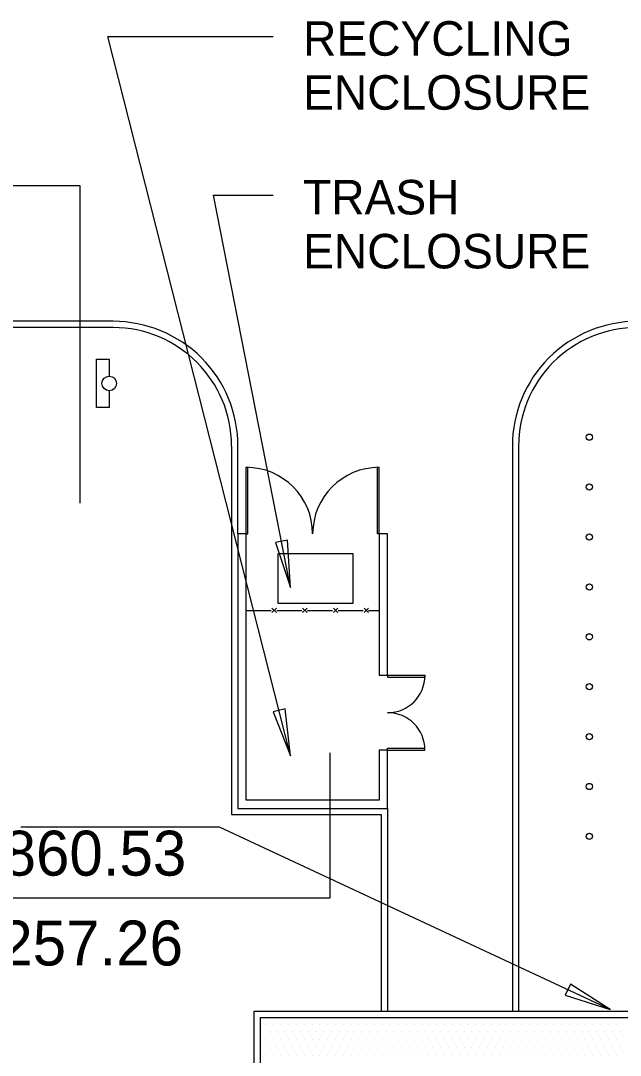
# Model space of a CAD drawing. Extents: x 6712138 to 6712574, y 1869536 to 1870160.
# Drawn here: x 6712232.5 to 6712280.5, y 1869836.3 to 1869919.2 of the extents above; entities that cross this region are included whole.
import ezdxf

# ---------------------------------------------------------------- set-up
doc = ezdxf.new("R2010")
doc.units = 0
for name, color, linetype in [('A-ANNO-TEXT', 7, 'Continuous'), ('A-DETL-GENF', 7, 'Continuous'), ('A-DETL-LW03', 7, 'Continuous'), ('A-DETL-MBND', 7, 'Continuous'), ('A-FLOR-OTLN', 7, 'Continuous'), ('A-FLOR-PATT', 7, 'Continuous'), ('C-PRKG-CONC', 7, 'Continuous'), ('C-SIGN-PARKING', 7, 'Continuous'), ('G-DETL-LW01', 7, 'Continuous'), ('G-DETL-LW03', 7, 'Continuous'), ('I-FURN', 7, 'Continuous'), ('I-WALL', 7, 'Continuous')]:
    doc.layers.add(name, color=color, linetype=linetype)

# ---------------------------------------------------------------- blocks, each defined once
blk = doc.blocks.new('Double-Flush - 10_ x 8_-113-xASP')
at = {"layer": 'A-DETL-MBND'}
for p, q in [((-5.333, 5.667), (-5.187, 5.667)), ((-5.333, 0.333), (-5.333, 5.667)), ((-5.187, 0.333), (-5.187, 5.667)), ((5.187, 0.333), (5.187, 5.665)), ((5.333, 0.333), (5.333, 5.667)), ((-5.333, 0.333), (-5.187, 0.333)), ((5.333, 0.333), (5.187, 0.333))]:
    blk.add_line(p, q, dxfattribs=at)
for centre, start, end in [((-5.333, 0.333), 0, 90), ((5.333, 0.333), 90, 180)]:
    blk.add_arc(centre, 5.333, start, end, dxfattribs=at)
blk = doc.blocks.new('Double-Flush - 6_ x 8_-133-xASP')
at = {"layer": 'A-DETL-MBND'}
for p, q in [((-3, 3.333), (-2.854, 3.333)), ((-3, 0.333), (-3, 3.333)), ((-2.854, 0.333), (-2.854, 3.333)), ((2.854, 0.333), (2.854, 3.33)), ((3, 0.333), (3, 3.333)), ((-3, 0.333), (-2.854, 0.333)), ((3, 0.333), (2.854, 0.333))]:
    blk.add_line(p, q, dxfattribs=at)
for centre, start, end in [((-3, 0.333), 0, 90), ((3, 0.333), 90, 180)]:
    blk.add_arc(centre, 3, start, end, dxfattribs=at)
blk = doc.blocks.new('Repeating Detail - Chain Link Fence-130-xASP')
at = {"layer": 'A-DETL-LW03'}
for p, q in [((0, 0), (2, 0)), ((2.073, 0.177), (2.427, -0.177)), ((2.427, 0.177), (2.073, -0.177))]:
    blk.add_line(p, q, dxfattribs=at)

msp = doc.modelspace()

# ---------------------------------------------------------------- linework, layer by layer
at = {"layer": 'A-ANNO-TEXT'}
for p, q in [((6712239.474, 1869917.929), (6712252.72, 1869917.929)), ((6712254.124, 1869860.283), (6712239.474, 1869917.929)), ((6712239.474, 1869917.929), (6712252.72, 1869917.929)), ((6712254.124, 1869860.283), (6712239.474, 1869917.929)), ((6712247.939, 1869905.209), (6712252.72, 1869905.209)), ((6712254.124, 1869873.783), (6712247.939, 1869905.209)), ((6712247.939, 1869905.209), (6712252.72, 1869905.209)), ((6712254.124, 1869873.783), (6712247.939, 1869905.209)), ((6712253.884, 1869877.558), (6712252.916, 1869877.367)), ((6712253.884, 1869877.558), (6712252.916, 1869877.367)), ((6712253.884, 1869877.558), (6712252.916, 1869877.367)), ((6712253.884, 1869877.558), (6712252.916, 1869877.367)), ((6712252.916, 1869877.367), (6712254.124, 1869873.783)), ((6712252.916, 1869877.367), (6712254.124, 1869873.783)), ((6712252.916, 1869877.367), (6712254.124, 1869873.783)), ((6712252.916, 1869877.367), (6712254.124, 1869873.783)), ((6712254.124, 1869873.783), (6712253.884, 1869877.558)), ((6712254.124, 1869873.783), (6712253.884, 1869877.558)), ((6712254.124, 1869873.783), (6712253.884, 1869877.558)), ((6712254.124, 1869873.783), (6712253.884, 1869877.558)), ((6712253.679, 1869864.039), (6712252.722, 1869863.796)), ((6712253.679, 1869864.039), (6712252.722, 1869863.796)), ((6712253.679, 1869864.039), (6712252.722, 1869863.796)), ((6712253.679, 1869864.039), (6712252.722, 1869863.796)), ((6712252.722, 1869863.796), (6712254.124, 1869860.283)), ((6712252.722, 1869863.796), (6712254.124, 1869860.283)), ((6712252.722, 1869863.796), (6712254.124, 1869860.283)), ((6712252.722, 1869863.796), (6712254.124, 1869860.283)), ((6712254.124, 1869860.283), (6712253.679, 1869864.039)), ((6712254.124, 1869860.283), (6712253.679, 1869864.039)), ((6712254.124, 1869860.283), (6712253.679, 1869864.039)), ((6712254.124, 1869860.283), (6712253.679, 1869864.039)), ((6712241.186, 1869854.578), (6712232.499, 1869854.578)), ((6712241.186, 1869854.578), (6712232.499, 1869854.578)), ((6712248.427, 1869854.578), (6712241.186, 1869854.578)), ((6712248.427, 1869854.578), (6712241.186, 1869854.578)), ((6712279.74, 1869839.953), (6712248.427, 1869854.578)), ((6712279.74, 1869839.953), (6712248.427, 1869854.578)), ((6712276.551, 1869841.987), (6712276.133, 1869841.093)), ((6712276.551, 1869841.987), (6712276.133, 1869841.093)), ((6712276.551, 1869841.987), (6712276.133, 1869841.093)), ((6712276.551, 1869841.987), (6712276.133, 1869841.093)), ((6712279.74, 1869839.953), (6712276.551, 1869841.987)), ((6712279.74, 1869839.953), (6712276.551, 1869841.987)), ((6712279.74, 1869839.953), (6712276.551, 1869841.987)), ((6712279.74, 1869839.953), (6712276.551, 1869841.987)), ((6712276.133, 1869841.093), (6712279.74, 1869839.953)), ((6712276.133, 1869841.093), (6712279.74, 1869839.953)), ((6712276.133, 1869841.093), (6712279.74, 1869839.953)), ((6712276.133, 1869841.093), (6712279.74, 1869839.953))]:
    msp.add_line(p, q, dxfattribs=at)
at = {"layer": 'A-DETL-GENF'}
for p, q in [((6712250.557, 1869878.073), (6712249.89, 1869878.073)), ((6712249.89, 1869878.073), (6712249.89, 1869856.073)), ((6712250.557, 1869856.739), (6712250.557, 1869878.073)), ((6712261.89, 1869878.073), (6712261.224, 1869878.073)), ((6712261.224, 1869878.073), (6712261.224, 1869866.739)), ((6712261.89, 1869866.739), (6712261.89, 1869878.073)), ((6712261.224, 1869866.739), (6712261.89, 1869866.739)), ((6712261.224, 1869860.739), (6712261.224, 1869856.739)), ((6712261.89, 1869860.739), (6712261.224, 1869860.739)), ((6712261.89, 1869856.073), (6712261.89, 1869860.739)), ((6712261.224, 1869856.739), (6712250.557, 1869856.739)), ((6712249.89, 1869856.073), (6712261.89, 1869856.073))]:
    msp.add_line(p, q, dxfattribs=at)
at = {"layer": 'A-FLOR-OTLN'}
for points in [[(6712251.183, 1869839.781), (6712251.183, 1869722.323), (6712419.14, 1869722.323), (6712419.14, 1869718.864), (6712468.641, 1869718.864), (6712468.641, 1869839.781)], [(6712251.683, 1869839.281), (6712251.683, 1869722.823), (6712419.64, 1869722.823), (6712419.64, 1869719.364), (6712468.141, 1869719.364), (6712468.141, 1869839.281)]]:
    msp.add_lwpolyline(points, close=True, dxfattribs=at)
at = {"layer": 'A-FLOR-PATT'}
for p, q in [((6712251.774, 1869838.157), (6712251.774, 1869838.157)), ((6712252.087, 1869838.782), (6712252.087, 1869838.782)), ((6712252.399, 1869838.157), (6712252.399, 1869838.157)), ((6712252.712, 1869838.782), (6712252.712, 1869838.782)), ((6712253.024, 1869838.157), (6712253.024, 1869838.157)), ((6712253.337, 1869838.782), (6712253.337, 1869838.782)), ((6712253.649, 1869838.157), (6712253.649, 1869838.157)), ((6712253.962, 1869838.782), (6712253.962, 1869838.782)), ((6712254.274, 1869838.157), (6712254.274, 1869838.157)), ((6712254.587, 1869838.782), (6712254.587, 1869838.782)), ((6712254.899, 1869838.157), (6712254.899, 1869838.157)), ((6712255.212, 1869838.782), (6712255.212, 1869838.782)), ((6712255.524, 1869838.157), (6712255.524, 1869838.157)), ((6712255.837, 1869838.782), (6712255.837, 1869838.782)), ((6712256.149, 1869838.157), (6712256.149, 1869838.157)), ((6712256.462, 1869838.782), (6712256.462, 1869838.782)), ((6712256.774, 1869838.157), (6712256.774, 1869838.157)), ((6712257.087, 1869838.782), (6712257.087, 1869838.782)), ((6712257.399, 1869838.157), (6712257.399, 1869838.157)), ((6712257.712, 1869838.782), (6712257.712, 1869838.782)), ((6712258.024, 1869838.157), (6712258.024, 1869838.157)), ((6712258.337, 1869838.782), (6712258.337, 1869838.782)), ((6712258.649, 1869838.157), (6712258.649, 1869838.157)), ((6712258.962, 1869838.782), (6712258.962, 1869838.782)), ((6712259.274, 1869838.157), (6712259.274, 1869838.157)), ((6712259.587, 1869838.782), (6712259.587, 1869838.782)), ((6712259.899, 1869838.157), (6712259.899, 1869838.157)), ((6712260.212, 1869838.782), (6712260.212, 1869838.782)), ((6712260.524, 1869838.157), (6712260.524, 1869838.157)), ((6712260.837, 1869838.782), (6712260.837, 1869838.782)), ((6712261.149, 1869838.157), (6712261.149, 1869838.157)), ((6712261.462, 1869838.782), (6712261.462, 1869838.782)), ((6712261.774, 1869838.157), (6712261.774, 1869838.157)), ((6712262.087, 1869838.782), (6712262.087, 1869838.782)), ((6712262.399, 1869838.157), (6712262.399, 1869838.157)), ((6712262.712, 1869838.782), (6712262.712, 1869838.782)), ((6712263.024, 1869838.157), (6712263.024, 1869838.157)), ((6712263.337, 1869838.782), (6712263.337, 1869838.782)), ((6712263.649, 1869838.157), (6712263.649, 1869838.157)), ((6712263.962, 1869838.782), (6712263.962, 1869838.782)), ((6712264.274, 1869838.157), (6712264.274, 1869838.157)), ((6712264.587, 1869838.782), (6712264.587, 1869838.782)), ((6712264.899, 1869838.157), (6712264.899, 1869838.157)), ((6712265.212, 1869838.782), (6712265.212, 1869838.782)), ((6712265.524, 1869838.157), (6712265.524, 1869838.157)), ((6712265.837, 1869838.782), (6712265.837, 1869838.782)), ((6712266.149, 1869838.157), (6712266.149, 1869838.157)), ((6712266.462, 1869838.782), (6712266.462, 1869838.782)), ((6712266.774, 1869838.157), (6712266.774, 1869838.157)), ((6712267.087, 1869838.782), (6712267.087, 1869838.782)), ((6712267.399, 1869838.157), (6712267.399, 1869838.157)), ((6712267.712, 1869838.782), (6712267.712, 1869838.782)), ((6712268.024, 1869838.157), (6712268.024, 1869838.157)), ((6712268.337, 1869838.782), (6712268.337, 1869838.782)), ((6712268.649, 1869838.157), (6712268.649, 1869838.157)), ((6712268.962, 1869838.782), (6712268.962, 1869838.782)), ((6712269.274, 1869838.157), (6712269.274, 1869838.157)), ((6712269.587, 1869838.782), (6712269.587, 1869838.782)), ((6712269.899, 1869838.157), (6712269.899, 1869838.157)), ((6712270.212, 1869838.782), (6712270.212, 1869838.782)), ((6712270.524, 1869838.157), (6712270.524, 1869838.157)), ((6712270.837, 1869838.782), (6712270.837, 1869838.782)), ((6712271.149, 1869838.157), (6712271.149, 1869838.157)), ((6712271.462, 1869838.782), (6712271.462, 1869838.782)), ((6712271.774, 1869838.157), (6712271.774, 1869838.157)), ((6712272.087, 1869838.782), (6712272.087, 1869838.782)), ((6712272.399, 1869838.157), (6712272.399, 1869838.157)), ((6712272.712, 1869838.782), (6712272.712, 1869838.782)), ((6712273.024, 1869838.157), (6712273.024, 1869838.157)), ((6712273.337, 1869838.782), (6712273.337, 1869838.782)), ((6712273.649, 1869838.157), (6712273.649, 1869838.157)), ((6712273.962, 1869838.782), (6712273.962, 1869838.782)), ((6712274.274, 1869838.157), (6712274.274, 1869838.157)), ((6712274.587, 1869838.782), (6712274.587, 1869838.782)), ((6712274.899, 1869838.157), (6712274.899, 1869838.157)), ((6712275.212, 1869838.782), (6712275.212, 1869838.782)), ((6712275.524, 1869838.157), (6712275.524, 1869838.157)), ((6712275.837, 1869838.782), (6712275.837, 1869838.782)), ((6712276.149, 1869838.157), (6712276.149, 1869838.157)), ((6712276.462, 1869838.782), (6712276.462, 1869838.782)), ((6712276.774, 1869838.157), (6712276.774, 1869838.157)), ((6712277.087, 1869838.782), (6712277.087, 1869838.782)), ((6712277.399, 1869838.157), (6712277.399, 1869838.157)), ((6712277.712, 1869838.782), (6712277.712, 1869838.782)), ((6712278.024, 1869838.157), (6712278.024, 1869838.157)), ((6712278.337, 1869838.782), (6712278.337, 1869838.782)), ((6712278.649, 1869838.157), (6712278.649, 1869838.157)), ((6712278.962, 1869838.782), (6712278.962, 1869838.782)), ((6712279.274, 1869838.157), (6712279.274, 1869838.157)), ((6712279.587, 1869838.782), (6712279.587, 1869838.782)), ((6712279.899, 1869838.157), (6712279.899, 1869838.157)), ((6712280.212, 1869838.782), (6712280.212, 1869838.782)), ((6712280.524, 1869838.157), (6712280.524, 1869838.157)), ((6712252.087, 1869837.532), (6712252.087, 1869837.532)), ((6712252.712, 1869837.532), (6712252.712, 1869837.532)), ((6712253.337, 1869837.532), (6712253.337, 1869837.532)), ((6712253.962, 1869837.532), (6712253.962, 1869837.532)), ((6712254.587, 1869837.532), (6712254.587, 1869837.532)), ((6712255.212, 1869837.532), (6712255.212, 1869837.532)), ((6712255.837, 1869837.532), (6712255.837, 1869837.532)), ((6712256.462, 1869837.532), (6712256.462, 1869837.532)), ((6712257.087, 1869837.532), (6712257.087, 1869837.532)), ((6712257.712, 1869837.532), (6712257.712, 1869837.532)), ((6712258.337, 1869837.532), (6712258.337, 1869837.532)), ((6712258.962, 1869837.532), (6712258.962, 1869837.532)), ((6712259.587, 1869837.532), (6712259.587, 1869837.532)), ((6712260.212, 1869837.532), (6712260.212, 1869837.532)), ((6712260.837, 1869837.532), (6712260.837, 1869837.532)), ((6712261.462, 1869837.532), (6712261.462, 1869837.532)), ((6712262.087, 1869837.532), (6712262.087, 1869837.532)), ((6712262.712, 1869837.532), (6712262.712, 1869837.532)), ((6712263.337, 1869837.532), (6712263.337, 1869837.532)), ((6712263.962, 1869837.532), (6712263.962, 1869837.532)), ((6712264.587, 1869837.532), (6712264.587, 1869837.532)), ((6712265.212, 1869837.532), (6712265.212, 1869837.532)), ((6712265.837, 1869837.532), (6712265.837, 1869837.532)), ((6712266.462, 1869837.532), (6712266.462, 1869837.532)), ((6712267.087, 1869837.532), (6712267.087, 1869837.532)), ((6712267.712, 1869837.532), (6712267.712, 1869837.532)), ((6712268.337, 1869837.532), (6712268.337, 1869837.532)), ((6712268.962, 1869837.532), (6712268.962, 1869837.532)), ((6712269.587, 1869837.532), (6712269.587, 1869837.532)), ((6712270.212, 1869837.532), (6712270.212, 1869837.532)), ((6712270.837, 1869837.532), (6712270.837, 1869837.532)), ((6712271.462, 1869837.532), (6712271.462, 1869837.532)), ((6712272.087, 1869837.532), (6712272.087, 1869837.532)), ((6712272.712, 1869837.532), (6712272.712, 1869837.532)), ((6712273.337, 1869837.532), (6712273.337, 1869837.532)), ((6712273.962, 1869837.532), (6712273.962, 1869837.532)), ((6712274.587, 1869837.532), (6712274.587, 1869837.532)), ((6712275.212, 1869837.532), (6712275.212, 1869837.532)), ((6712275.837, 1869837.532), (6712275.837, 1869837.532)), ((6712276.462, 1869837.532), (6712276.462, 1869837.532)), ((6712277.087, 1869837.532), (6712277.087, 1869837.532)), ((6712277.712, 1869837.532), (6712277.712, 1869837.532)), ((6712278.337, 1869837.532), (6712278.337, 1869837.532)), ((6712278.962, 1869837.532), (6712278.962, 1869837.532)), ((6712279.587, 1869837.532), (6712279.587, 1869837.532)), ((6712280.212, 1869837.532), (6712280.212, 1869837.532)), ((6712251.774, 1869836.907), (6712251.774, 1869836.907)), ((6712252.399, 1869836.907), (6712252.399, 1869836.907)), ((6712253.024, 1869836.907), (6712253.024, 1869836.907)), ((6712253.649, 1869836.907), (6712253.649, 1869836.907)), ((6712254.274, 1869836.907), (6712254.274, 1869836.907)), ((6712254.899, 1869836.907), (6712254.899, 1869836.907)), ((6712255.524, 1869836.907), (6712255.524, 1869836.907)), ((6712256.149, 1869836.907), (6712256.149, 1869836.907)), ((6712256.774, 1869836.907), (6712256.774, 1869836.907)), ((6712257.399, 1869836.907), (6712257.399, 1869836.907)), ((6712258.024, 1869836.907), (6712258.024, 1869836.907)), ((6712258.649, 1869836.907), (6712258.649, 1869836.907)), ((6712259.274, 1869836.907), (6712259.274, 1869836.907)), ((6712259.899, 1869836.907), (6712259.899, 1869836.907)), ((6712260.524, 1869836.907), (6712260.524, 1869836.907)), ((6712261.149, 1869836.907), (6712261.149, 1869836.907)), ((6712261.774, 1869836.907), (6712261.774, 1869836.907)), ((6712262.399, 1869836.907), (6712262.399, 1869836.907)), ((6712263.024, 1869836.907), (6712263.024, 1869836.907)), ((6712263.649, 1869836.907), (6712263.649, 1869836.907)), ((6712264.274, 1869836.907), (6712264.274, 1869836.907)), ((6712264.899, 1869836.907), (6712264.899, 1869836.907)), ((6712265.524, 1869836.907), (6712265.524, 1869836.907)), ((6712266.149, 1869836.907), (6712266.149, 1869836.907)), ((6712266.774, 1869836.907), (6712266.774, 1869836.907)), ((6712267.399, 1869836.907), (6712267.399, 1869836.907)), ((6712268.024, 1869836.907), (6712268.024, 1869836.907)), ((6712268.649, 1869836.907), (6712268.649, 1869836.907)), ((6712269.274, 1869836.907), (6712269.274, 1869836.907)), ((6712269.899, 1869836.907), (6712269.899, 1869836.907)), ((6712270.524, 1869836.907), (6712270.524, 1869836.907)), ((6712271.149, 1869836.907), (6712271.149, 1869836.907)), ((6712271.774, 1869836.907), (6712271.774, 1869836.907)), ((6712272.399, 1869836.907), (6712272.399, 1869836.907)), ((6712273.024, 1869836.907), (6712273.024, 1869836.907)), ((6712273.649, 1869836.907), (6712273.649, 1869836.907)), ((6712274.274, 1869836.907), (6712274.274, 1869836.907)), ((6712274.899, 1869836.907), (6712274.899, 1869836.907)), ((6712275.524, 1869836.907), (6712275.524, 1869836.907)), ((6712276.149, 1869836.907), (6712276.149, 1869836.907)), ((6712276.774, 1869836.907), (6712276.774, 1869836.907)), ((6712277.399, 1869836.907), (6712277.399, 1869836.907)), ((6712278.024, 1869836.907), (6712278.024, 1869836.907)), ((6712278.649, 1869836.907), (6712278.649, 1869836.907)), ((6712279.274, 1869836.907), (6712279.274, 1869836.907)), ((6712279.899, 1869836.907), (6712279.899, 1869836.907)), ((6712280.524, 1869836.907), (6712280.524, 1869836.907)), ((6712252.087, 1869836.282), (6712252.087, 1869836.282)), ((6712252.712, 1869836.282), (6712252.712, 1869836.282)), ((6712253.337, 1869836.282), (6712253.337, 1869836.282)), ((6712253.962, 1869836.282), (6712253.962, 1869836.282)), ((6712254.587, 1869836.282), (6712254.587, 1869836.282)), ((6712255.212, 1869836.282), (6712255.212, 1869836.282)), ((6712255.837, 1869836.282), (6712255.837, 1869836.282)), ((6712256.462, 1869836.282), (6712256.462, 1869836.282)), ((6712257.087, 1869836.282), (6712257.087, 1869836.282)), ((6712257.712, 1869836.282), (6712257.712, 1869836.282)), ((6712258.337, 1869836.282), (6712258.337, 1869836.282)), ((6712258.962, 1869836.282), (6712258.962, 1869836.282)), ((6712259.587, 1869836.282), (6712259.587, 1869836.282)), ((6712260.212, 1869836.282), (6712260.212, 1869836.282)), ((6712260.837, 1869836.282), (6712260.837, 1869836.282)), ((6712261.462, 1869836.282), (6712261.462, 1869836.282)), ((6712262.087, 1869836.282), (6712262.087, 1869836.282)), ((6712262.712, 1869836.282), (6712262.712, 1869836.282)), ((6712263.337, 1869836.282), (6712263.337, 1869836.282)), ((6712263.962, 1869836.282), (6712263.962, 1869836.282)), ((6712264.587, 1869836.282), (6712264.587, 1869836.282)), ((6712265.212, 1869836.282), (6712265.212, 1869836.282)), ((6712265.837, 1869836.282), (6712265.837, 1869836.282)), ((6712266.462, 1869836.282), (6712266.462, 1869836.282)), ((6712267.087, 1869836.282), (6712267.087, 1869836.282)), ((6712267.712, 1869836.282), (6712267.712, 1869836.282)), ((6712268.337, 1869836.282), (6712268.337, 1869836.282)), ((6712268.962, 1869836.282), (6712268.962, 1869836.282)), ((6712269.587, 1869836.282), (6712269.587, 1869836.282)), ((6712270.212, 1869836.282), (6712270.212, 1869836.282)), ((6712270.837, 1869836.282), (6712270.837, 1869836.282)), ((6712271.462, 1869836.282), (6712271.462, 1869836.282)), ((6712272.087, 1869836.282), (6712272.087, 1869836.282)), ((6712272.712, 1869836.282), (6712272.712, 1869836.282)), ((6712273.337, 1869836.282), (6712273.337, 1869836.282)), ((6712273.962, 1869836.282), (6712273.962, 1869836.282)), ((6712274.587, 1869836.282), (6712274.587, 1869836.282)), ((6712275.212, 1869836.282), (6712275.212, 1869836.282)), ((6712275.837, 1869836.282), (6712275.837, 1869836.282)), ((6712276.462, 1869836.282), (6712276.462, 1869836.282)), ((6712277.087, 1869836.282), (6712277.087, 1869836.282)), ((6712277.712, 1869836.282), (6712277.712, 1869836.282)), ((6712278.337, 1869836.282), (6712278.337, 1869836.282)), ((6712278.962, 1869836.282), (6712278.962, 1869836.282)), ((6712279.587, 1869836.282), (6712279.587, 1869836.282)), ((6712280.212, 1869836.282), (6712280.212, 1869836.282))]:
    msp.add_line(p, q, dxfattribs=at)
at = {"layer": 'C-PRKG-CONC'}
for p, q in [((6712239.904, 1869895.107), (6712197.987, 1869895.107)), ((6712239.904, 1869894.607), (6712197.987, 1869894.607)), ((6712249.39, 1869885.107), (6712249.39, 1869855.573)), ((6712249.39, 1869884.59), (6712249.39, 1869855.573)), ((6712249.89, 1869878.073), (6712249.904, 1869885.088)), ((6712271.89, 1869885.107), (6712271.891, 1869839.781)), ((6712272.39, 1869885.107), (6712272.391, 1869839.781)), ((6712271.89, 1869884.406), (6712271.891, 1869839.781)), ((6712272.39, 1869884.406), (6712272.391, 1869839.781)), ((6712249.39, 1869855.573), (6712261.39, 1869855.573)), ((6712249.39, 1869855.573), (6712261.39, 1869855.573)), ((6712261.39, 1869855.573), (6712261.391, 1869839.781)), ((6712261.39, 1869855.573), (6712261.391, 1869839.781)), ((6712261.89, 1869856.073), (6712261.891, 1869839.781)), ((6712261.89, 1869856.073), (6712261.891, 1869839.781))]:
    msp.add_line(p, q, dxfattribs=at)
for centre, radius, start, end in [((6712239.89, 1869885.107), 9.5, 0, 90), ((6712239.904, 1869885.107), 10, 359.8909, 90), ((6712281.89, 1869885.107), 10, 90, 180.00085), ((6712281.89, 1869885.107), 9.5, 90, 180.00085)]:
    msp.add_arc(centre, radius, start, end, dxfattribs=at)
at = {"layer": 'C-SIGN-PARKING'}
msp.add_lwpolyline([(6712239.59, 1869889.542), (6712239.59, 1869888.19), (6712238.556, 1869888.19), (6712238.556, 1869892.066), (6712239.59, 1869892.066), (6712239.59, 1869890.714)], dxfattribs=at)
msp.add_circle((6712239.59, 1869890.128), 0.586, dxfattribs=at)
at = {"layer": 'G-DETL-LW01'}
for p, q in [((6712253.117, 1869872.489), (6712253.117, 1869876.489)), ((6712253.117, 1869876.489), (6712259.117, 1869876.489)), ((6712259.117, 1869876.489), (6712259.117, 1869872.489)), ((6712259.117, 1869872.489), (6712253.117, 1869872.489))]:
    msp.add_line(p, q, dxfattribs=at)
at = {"layer": 'G-DETL-LW03'}
msp.add_line((6712260.359, 1869871.939), (6712261.224, 1869871.939), dxfattribs=at)
msp.add_line((6712260.359, 1869871.939), (6712261.224, 1869871.939), dxfattribs=at)
msp.add_line((6712260.359, 1869871.939), (6712261.224, 1869871.939), dxfattribs=at)
at = {"layer": 'I-FURN'}
for centre in [(6712278.064, 1869885.823), (6712278.064, 1869881.823), (6712278.064, 1869877.823), (6712278.064, 1869873.823), (6712278.064, 1869869.823), (6712278.064, 1869865.823), (6712278.064, 1869861.823), (6712278.064, 1869857.823), (6712278.064, 1869853.823)]:
    msp.add_circle(centre, 0.25, dxfattribs=at)
at = {"layer": 'I-WALL'}
for points in [[(6712237.26, 1869905.96), (6712195.18, 1869905.96)], [(6712237.26, 1869880.525), (6712237.26, 1869905.96)], [(6712257.26, 1869860.525), (6712257.26, 1869848.881)], [(6712257.26, 1869848.881), (6712215.52, 1869848.881)]]:
    msp.add_lwpolyline(points, dxfattribs=at)

# ---------------------------------------------------------------- block references
at = {"layer": 'A-DETL-GENF', "xscale": 1.000002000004, "yscale": 1.000002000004}
for p in [(6712250.557, 1869871.939), (6712253.015, 1869871.939), (6712255.474, 1869871.939), (6712257.932, 1869871.939)]:
    msp.add_blockref('Repeating Detail - Chain Link Fence-130-xASP', p, dxfattribs=at)
at = {"layer": 'A-DETL-MBND', "xscale": 1.000002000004, "yscale": 1.000002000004}
msp.add_blockref('Double-Flush - 10_ x 8_-113-xASP', (6712255.89, 1869877.739), dxfattribs=at)
at = {"layer": 'A-DETL-MBND', "xscale": 1.000002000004, "yscale": 1.000002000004, "rotation": -90.00000000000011}
msp.add_blockref('Double-Flush - 6_ x 8_-133-xASP', (6712261.557, 1869863.739), dxfattribs=at)

# ---------------------------------------------------------------- texts
at = {"layer": 'A-ANNO-TEXT'}
for s, p in [('RECYCLING', (6712255.12, 1869916.393)), ('RECYCLING', (6712255.12, 1869916.393)), ('ENCLOSURE', (6712255.12, 1869912.066)), ('ENCLOSURE', (6712255.12, 1869912.066)), ('TRASH', (6712255.12, 1869903.673)), ('TRASH', (6712255.12, 1869903.673)), ('ENCLOSURE', (6712255.12, 1869899.346)), ('ENCLOSURE', (6712255.12, 1869899.346))]:
    msp.add_text(s, height=2.7662, dxfattribs=at).set_placement(p)
at = {"layer": 'I-WALL'}
for s, p in [('N 1869860.53', (6712215.52, 1869850.681)), ('E 6712257.26', (6712215.52, 1869843.481))]:
    msp.add_text(s, height=3.6, dxfattribs=at).set_placement(p)

doc.saveas('drawing.dxf')
